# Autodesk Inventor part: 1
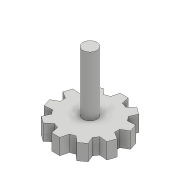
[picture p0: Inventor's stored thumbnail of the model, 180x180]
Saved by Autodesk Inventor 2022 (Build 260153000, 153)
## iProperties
Created: 2017-05
Part Number: 1
Material: Generic
Document SubType Name: Modeling
Designer: CADCIM 00
Density: 1 g/cm^3
Appearance: Default
Author: CADCIM 00
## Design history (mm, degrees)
sketch "Sketch1"
  geometry: L1 (-3.765, 16.614)-(-2.561, 21.495); L2 (-2.561, 21.495)-(2.518, 21.495); L3 (2.518, 21.495)-(3.613, 16.648); L4 (-12.811, 11.228)-(-14.706, 15.884); L5 (-14.706, 15.884)-(-10.598, 18.87); L6 (-10.598, 18.87)-(-6.862, 15.592); L7 (-16.964, 1.554)-(-21.234, 4.206); L8 (-21.234, 4.206)-(-19.665, 9.037); L9 (-19.665, 9.037)-(-14.716, 8.581); L10 (-14.637, -8.714)-(-19.651, -9.078); L11 (-19.651, -9.078)-(-21.221, -4.248); L12 (-21.221, -4.248)-(-16.949, -1.708); L13 (-6.72, -15.654)-(-10.562, -18.895); L14 (-10.562, -18.895)-(-14.671, -15.91); L15 (-14.671, -15.91)-(-12.708, -11.344); L16 (3.765, -16.614)-(2.561, -21.495); L17 (2.561, -21.495)-(-2.518, -21.495); L18 (-2.518, -21.495)-(-3.613, -16.648); L19 (12.811, -11.228)-(14.706, -15.884); L20 (14.706, -15.884)-(10.598, -18.87); L21 (10.598, -18.87)-(6.862, -15.592); L22 (16.964, -1.554)-(21.234, -4.206); L23 (21.234, -4.206)-(19.665, -9.037); L24 (19.665, -9.037)-(14.716, -8.581); L25 (14.637, 8.714)-(19.651, 9.078); L26 (19.651, 9.078)-(21.221, 4.248); L27 (21.221, 4.248)-(16.949, 1.708); L28 (6.72, 15.654)-(10.562, 18.895); L29 (10.562, 18.895)-(14.671, 15.91); L30 (14.671, 15.91)-(12.708, 11.344); A1 r 17.035 centre (0, 0) between (-3.765, 16.614) and (-6.862, 15.592); A2 r 17.035 centre (0, 0) between (-12.811, 11.228) and (-14.716, 8.581); A3 r 17.035 centre (0, 0) between (-16.964, 1.554) and (-16.949, -1.708); A4 r 17.035 centre (0, 0) between (-14.637, -8.714) and (-12.708, -11.344); A5 r 17.035 centre (0, 0) between (-6.72, -15.654) and (-3.613, -16.648); A6 r 17.035 centre (0, 0) between (3.765, -16.614) and (6.862, -15.592); A7 r 17.035 centre (0, 0) between (12.811, -11.228) and (14.716, -8.581); A8 r 17.035 centre (0, 0) between (16.964, -1.554) and (16.949, 1.708); A9 r 17.035 centre (0, 0) between (14.637, 8.714) and (12.708, 11.344); A10 r 17.035 centre (0, 0) between (6.72, 15.654) and (3.613, 16.648); 1 further point
  constraints: 60 end point, 20 point on circle, 10 centre point, 1 coincident, 1 horizontal, 71 other
  dimensions: "d2" = 360 deg dimension on A1.centre L1.start (derived)
extrude "Extrusion1" new body sketch "Sketch1" distance "d4" = 10; taper "d5" = 0 deg
sketch "Sketch2"
  geometry: C1 r 4.406 at (0, 0); 1 further point
  constraints: 1 centre point, 1 coincident
extrude "Extrusion2" join sketch "Sketch2" distance "d6" = 37.5; taper "d7" = 0 deg
body "Solid1"
